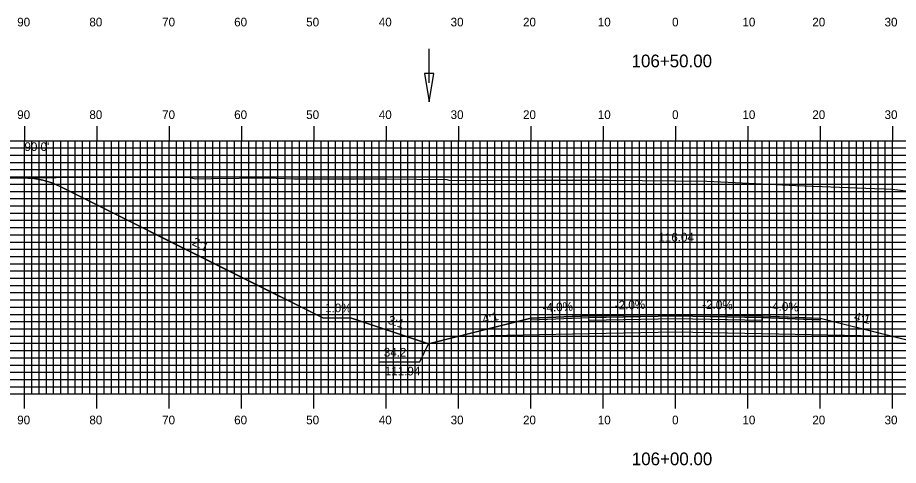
# Model space of a CAD drawing. Extents: x 1768087 to 1768430, y 442591 to 442811.
# Drawn here: x 1768162 to 1768283.8, y 442653.8 to 442715.7 of the extents above; entities that cross this region are included whole.
import ezdxf

# ---------------------------------------------------------------- set-up
doc = ezdxf.new("R2010")
doc.units = 0
for name, color, linetype in [('ANNOTATION', 7, 'Continuous'), ('D_Drainage_Ditch_Line', 7, 'Continuous'), ('D_Roadway_Centerline', 7, 'Continuous'), ('D_Roadway_Centerline_Text', 7, 'Continuous'), ('D_Roadway_Edge_Shoulder', 7, 'Continuous'), ('D_Roadway_Edge_TW', 7, 'Continuous'), ('D_Roadway_Pavement', 7, 'Continuous'), ('D_Roadway_SlopeLines', 7, 'Continuous'), ('D_Roadway_SubGrade', 7, 'Continuous'), ('D_Text_Standard', 7, 'Continuous'), ('H_V ANNOTATION', 7, 'Continuous'), ('MAJOR', 7, 'Continuous'), ('MINOR', 7, 'Continuous'), ('S_Roadway_Centerline', 7, 'Continuous')]:
    doc.layers.add(name, color=color, linetype=linetype)

msp = doc.modelspace()

# ---------------------------------------------------------------- linework, layer by layer
at = {"layer": 'ANNOTATION'}
msp.add_lwpolyline([(1768211.89, 442668.1), (1768217.58, 442668.1), (1768218.79, 442670.6)], dxfattribs=at)
at = {"layer": 'D_Drainage_Ditch_Line'}
msp.add_line((1768218.9, 442706.66), (1768218.9, 442711.36), dxfattribs=at)
msp.add_lwpolyline([(1768219.56, 442707.97), (1768218.24, 442707.97), (1768218.9, 442704.03)], close=True, dxfattribs=at)
at = {"layer": 'D_Roadway_Centerline'}
msp.add_lwpolyline([(1768162.96, 442693.52), (1768163.41, 442693.5), (1768164.21, 442693.46), (1768164.78, 442693.35), (1768165.46, 442693.23), (1768166.44, 442692.93), (1768166.71, 442692.85), (1768167.25, 442692.61), (1768167.96, 442692.3), (1768192.44, 442680.06), (1768204.19, 442674.19), (1768208.16, 442674.15), (1768213.42, 442672.39), (1768218.79, 442670.6), (1768222.79, 442671.6), (1768222.79, 442671.6), (1768230.68, 442673.58), (1768232.96, 442674.15), (1768232.96, 442674.15), (1768232.96, 442674.15), (1768240.96, 442674.47), (1768240.97, 442674.47), (1768250.05, 442674.65), (1768252.96, 442674.71), (1768264.96, 442674.47), (1768270.99, 442674.23), (1768272.96, 442674.15), (1768277.03, 442673.13), (1768283.14, 442671.6), (1768283.14, 442671.6), (1768287.14, 442670.6)], dxfattribs=at)
at = {"layer": 'D_Roadway_Edge_Shoulder'}
for points in [[(1768240.96, 442674.47), (1768232.96, 442674.15), (1768232.96, 442673.9), (1768240.96, 442674.22)], [(1768264.96, 442674.47), (1768272.96, 442674.15), (1768272.96, 442673.9), (1768264.96, 442674.22)]]:
    msp.add_lwpolyline(points, close=True, dxfattribs=at)
at = {"layer": 'D_Roadway_Edge_TW'}
msp.add_lwpolyline([(1768240.96, 442674.22), (1768240.96, 442674.47), (1768252.96, 442674.71), (1768264.96, 442674.47), (1768264.96, 442674.22), (1768252.96, 442674.46)], close=True, dxfattribs=at)
at = {"layer": 'D_Roadway_Pavement'}
msp.add_lwpolyline([(1768240.96, 442673.8), (1768240.96, 442674.22), (1768252.96, 442674.46), (1768264.96, 442674.22), (1768264.96, 442673.8), (1768252.96, 442674.04)], close=True, dxfattribs=at)
at = {"layer": 'D_Roadway_SlopeLines'}
for points in [[(1768208.16, 442674.15), (1768204.19, 442674.19), (1768167.96, 442692.3), (1768166.71, 442692.85), (1768165.46, 442693.23), (1768164.21, 442693.46), (1768162.96, 442693.52)], [(1768218.79, 442670.6), (1768208.16, 442674.15)], [(1768232.96, 442674.15), (1768218.79, 442670.6)], [(1768272.96, 442674.15), (1768287.14, 442670.6)]]:
    msp.add_lwpolyline(points, dxfattribs=at)
at = {"layer": 'D_Roadway_SubGrade'}
msp.add_lwpolyline([(1768240.96, 442671.97), (1768222.79, 442671.6), (1768232.96, 442674.15), (1768232.96, 442673.9), (1768240.96, 442674.22), (1768252.96, 442674.46), (1768264.96, 442674.22), (1768272.96, 442673.9), (1768272.96, 442674.15), (1768283.14, 442671.6), (1768264.96, 442671.97), (1768252.96, 442672.21)], close=True, dxfattribs=at)
at = {"layer": 'MAJOR'}
for p, q in [((1768162.96, 442700.67), (1768162.96, 442698.67)), ((1768172.96, 442700.67), (1768172.96, 442698.67)), ((1768182.96, 442700.67), (1768182.96, 442698.67)), ((1768192.96, 442700.67), (1768192.96, 442698.67)), ((1768202.96, 442700.67), (1768202.96, 442698.67)), ((1768212.96, 442700.67), (1768212.96, 442698.67)), ((1768222.96, 442700.67), (1768222.96, 442698.67)), ((1768232.96, 442700.67), (1768232.96, 442698.67)), ((1768242.96, 442700.67), (1768242.96, 442698.67)), ((1768252.96, 442700.67), (1768252.96, 442698.67)), ((1768262.96, 442700.67), (1768262.96, 442698.67)), ((1768272.96, 442700.67), (1768272.96, 442698.67)), ((1768282.96, 442700.67), (1768282.96, 442698.67)), ((1768112.96, 442698.67), (1768392.96, 442698.67)), ((1768112.96, 442698.67), (1768392.96, 442698.67)), ((1768162.96, 442663.67), (1768162.96, 442698.67)), ((1768172.96, 442663.67), (1768172.96, 442698.67)), ((1768182.96, 442663.67), (1768182.96, 442698.67)), ((1768192.96, 442663.67), (1768192.96, 442698.67)), ((1768202.96, 442663.67), (1768202.96, 442698.67)), ((1768212.96, 442663.67), (1768212.96, 442698.67)), ((1768222.96, 442663.67), (1768222.96, 442698.67)), ((1768232.96, 442663.67), (1768232.96, 442698.67)), ((1768242.96, 442663.67), (1768242.96, 442698.67)), ((1768252.96, 442663.67), (1768252.96, 442698.67)), ((1768262.96, 442663.67), (1768262.96, 442698.67)), ((1768272.96, 442663.67), (1768272.96, 442698.67)), ((1768282.96, 442663.67), (1768282.96, 442698.67)), ((1768112.96, 442693.67), (1768392.96, 442693.67)), ((1768112.96, 442688.67), (1768392.96, 442688.67)), ((1768112.96, 442683.67), (1768392.96, 442683.67)), ((1768112.96, 442678.67), (1768392.96, 442678.67)), ((1768112.96, 442673.67), (1768392.96, 442673.67)), ((1768112.96, 442668.67), (1768392.96, 442668.67)), ((1768112.96, 442663.67), (1768392.96, 442663.67)), ((1768112.96, 442663.67), (1768392.96, 442663.67)), ((1768162.96, 442661.66), (1768162.96, 442663.67)), ((1768172.96, 442661.66), (1768172.96, 442663.67)), ((1768182.96, 442661.66), (1768182.96, 442663.67)), ((1768192.96, 442661.66), (1768192.96, 442663.67)), ((1768202.96, 442661.66), (1768202.96, 442663.67)), ((1768212.96, 442661.66), (1768212.96, 442663.67)), ((1768222.96, 442661.66), (1768222.96, 442663.67)), ((1768232.96, 442661.66), (1768232.96, 442663.67)), ((1768242.96, 442661.66), (1768242.96, 442663.67)), ((1768252.96, 442661.66), (1768252.96, 442663.67)), ((1768262.96, 442661.66), (1768262.96, 442663.67)), ((1768272.96, 442661.66), (1768272.96, 442663.67)), ((1768282.96, 442661.66), (1768282.96, 442663.67))]:
    msp.add_line(p, q, dxfattribs=at)
at = {"layer": 'MINOR'}
for p, q in [((1768163.96, 442663.67), (1768163.96, 442698.67)), ((1768164.96, 442663.67), (1768164.96, 442698.67)), ((1768165.96, 442663.67), (1768165.96, 442698.67)), ((1768166.96, 442663.67), (1768166.96, 442698.67)), ((1768167.96, 442663.67), (1768167.96, 442698.67)), ((1768168.96, 442663.67), (1768168.96, 442698.67)), ((1768169.96, 442663.67), (1768169.96, 442698.67)), ((1768170.96, 442663.67), (1768170.96, 442698.67)), ((1768171.96, 442663.67), (1768171.96, 442698.67)), ((1768173.96, 442663.67), (1768173.96, 442698.67)), ((1768174.96, 442663.67), (1768174.96, 442698.67)), ((1768175.96, 442663.67), (1768175.96, 442698.67)), ((1768176.96, 442663.67), (1768176.96, 442698.67)), ((1768177.96, 442663.67), (1768177.96, 442698.67)), ((1768178.96, 442663.67), (1768178.96, 442698.67)), ((1768179.96, 442663.67), (1768179.96, 442698.67)), ((1768180.96, 442663.67), (1768180.96, 442698.67)), ((1768181.96, 442663.67), (1768181.96, 442698.67)), ((1768183.96, 442663.67), (1768183.96, 442698.67)), ((1768184.96, 442663.67), (1768184.96, 442698.67)), ((1768185.96, 442663.67), (1768185.96, 442698.67)), ((1768186.96, 442663.67), (1768186.96, 442698.67)), ((1768187.96, 442663.67), (1768187.96, 442698.67)), ((1768188.96, 442663.67), (1768188.96, 442698.67)), ((1768189.96, 442663.67), (1768189.96, 442698.67)), ((1768190.96, 442663.67), (1768190.96, 442698.67)), ((1768191.96, 442663.67), (1768191.96, 442698.67)), ((1768193.96, 442663.67), (1768193.96, 442698.67)), ((1768194.96, 442663.67), (1768194.96, 442698.67)), ((1768195.96, 442663.67), (1768195.96, 442698.67)), ((1768196.96, 442663.67), (1768196.96, 442698.67)), ((1768197.96, 442663.67), (1768197.96, 442698.67)), ((1768198.96, 442663.67), (1768198.96, 442698.67)), ((1768199.96, 442663.67), (1768199.96, 442698.67)), ((1768200.96, 442663.67), (1768200.96, 442698.67)), ((1768201.96, 442663.67), (1768201.96, 442698.67)), ((1768203.96, 442663.67), (1768203.96, 442698.67)), ((1768204.96, 442663.67), (1768204.96, 442698.67)), ((1768205.96, 442663.67), (1768205.96, 442698.67)), ((1768206.96, 442663.67), (1768206.96, 442698.67)), ((1768207.96, 442663.67), (1768207.96, 442698.67)), ((1768208.96, 442663.67), (1768208.96, 442698.67)), ((1768209.96, 442663.67), (1768209.96, 442698.67)), ((1768210.96, 442663.67), (1768210.96, 442698.67)), ((1768211.96, 442663.67), (1768211.96, 442698.67)), ((1768213.96, 442663.67), (1768213.96, 442698.67)), ((1768214.96, 442663.67), (1768214.96, 442698.67)), ((1768215.96, 442663.67), (1768215.96, 442698.67)), ((1768216.96, 442663.67), (1768216.96, 442698.67)), ((1768217.96, 442663.67), (1768217.96, 442698.67)), ((1768218.96, 442663.67), (1768218.96, 442698.67)), ((1768219.96, 442663.67), (1768219.96, 442698.67)), ((1768220.96, 442663.67), (1768220.96, 442698.67)), ((1768221.96, 442663.67), (1768221.96, 442698.67)), ((1768223.96, 442663.67), (1768223.96, 442698.67)), ((1768224.96, 442663.67), (1768224.96, 442698.67)), ((1768225.96, 442663.67), (1768225.96, 442698.67)), ((1768226.96, 442663.67), (1768226.96, 442698.67)), ((1768227.96, 442663.67), (1768227.96, 442698.67)), ((1768228.96, 442663.67), (1768228.96, 442698.67)), ((1768229.96, 442663.67), (1768229.96, 442698.67)), ((1768230.96, 442663.67), (1768230.96, 442698.67)), ((1768231.96, 442663.67), (1768231.96, 442698.67)), ((1768233.96, 442663.67), (1768233.96, 442698.67)), ((1768234.96, 442663.67), (1768234.96, 442698.67)), ((1768235.96, 442663.67), (1768235.96, 442698.67)), ((1768236.96, 442663.67), (1768236.96, 442698.67)), ((1768237.96, 442663.67), (1768237.96, 442698.67)), ((1768238.96, 442663.67), (1768238.96, 442698.67)), ((1768239.96, 442663.67), (1768239.96, 442698.67)), ((1768240.96, 442663.67), (1768240.96, 442698.67)), ((1768241.96, 442663.67), (1768241.96, 442698.67)), ((1768243.96, 442663.67), (1768243.96, 442698.67)), ((1768244.96, 442663.67), (1768244.96, 442698.67)), ((1768245.96, 442663.67), (1768245.96, 442698.67)), ((1768246.96, 442663.67), (1768246.96, 442698.67)), ((1768247.96, 442663.67), (1768247.96, 442698.67)), ((1768248.96, 442663.67), (1768248.96, 442698.67)), ((1768249.96, 442663.67), (1768249.96, 442698.67)), ((1768250.96, 442663.67), (1768250.96, 442698.67)), ((1768251.96, 442663.67), (1768251.96, 442698.67)), ((1768253.96, 442663.67), (1768253.96, 442698.67)), ((1768254.96, 442663.67), (1768254.96, 442698.67)), ((1768255.96, 442663.67), (1768255.96, 442698.67)), ((1768256.96, 442663.67), (1768256.96, 442698.67)), ((1768257.96, 442663.67), (1768257.96, 442698.67)), ((1768258.96, 442663.67), (1768258.96, 442698.67)), ((1768259.96, 442663.67), (1768259.96, 442698.67)), ((1768260.96, 442663.67), (1768260.96, 442698.67)), ((1768261.96, 442663.67), (1768261.96, 442698.67)), ((1768263.96, 442663.67), (1768263.96, 442698.67)), ((1768264.96, 442663.67), (1768264.96, 442698.67)), ((1768265.96, 442663.67), (1768265.96, 442698.67)), ((1768266.96, 442663.67), (1768266.96, 442698.67)), ((1768267.96, 442663.67), (1768267.96, 442698.67)), ((1768268.96, 442663.67), (1768268.96, 442698.67)), ((1768269.96, 442663.67), (1768269.96, 442698.67)), ((1768270.96, 442663.67), (1768270.96, 442698.67)), ((1768271.96, 442663.67), (1768271.96, 442698.67)), ((1768273.96, 442663.67), (1768273.96, 442698.67)), ((1768274.96, 442663.67), (1768274.96, 442698.67)), ((1768275.96, 442663.67), (1768275.96, 442698.67)), ((1768276.96, 442663.67), (1768276.96, 442698.67)), ((1768277.96, 442663.67), (1768277.96, 442698.67)), ((1768278.96, 442663.67), (1768278.96, 442698.67)), ((1768279.96, 442663.67), (1768279.96, 442698.67)), ((1768280.96, 442663.67), (1768280.96, 442698.67)), ((1768281.96, 442663.67), (1768281.96, 442698.67)), ((1768112.96, 442697.67), (1768392.96, 442697.67)), ((1768112.96, 442696.67), (1768392.96, 442696.67)), ((1768112.96, 442695.67), (1768392.96, 442695.67)), ((1768112.96, 442694.67), (1768392.96, 442694.67)), ((1768112.96, 442692.67), (1768392.96, 442692.67)), ((1768112.96, 442691.67), (1768392.96, 442691.67)), ((1768112.96, 442690.67), (1768392.96, 442690.67)), ((1768112.96, 442689.67), (1768392.96, 442689.67)), ((1768112.96, 442687.67), (1768392.96, 442687.67)), ((1768112.96, 442686.67), (1768392.96, 442686.67)), ((1768112.96, 442685.67), (1768392.96, 442685.67)), ((1768112.96, 442684.67), (1768392.96, 442684.67)), ((1768112.96, 442682.67), (1768392.96, 442682.67)), ((1768112.96, 442681.67), (1768392.96, 442681.67)), ((1768112.96, 442680.67), (1768392.96, 442680.67)), ((1768112.96, 442679.67), (1768392.96, 442679.67)), ((1768112.96, 442677.67), (1768392.96, 442677.67)), ((1768112.96, 442676.67), (1768392.96, 442676.67)), ((1768112.96, 442675.67), (1768392.96, 442675.67)), ((1768112.96, 442674.67), (1768392.96, 442674.67)), ((1768112.96, 442672.67), (1768392.96, 442672.67)), ((1768112.96, 442671.67), (1768392.96, 442671.67)), ((1768112.96, 442670.67), (1768392.96, 442670.67)), ((1768112.96, 442669.67), (1768392.96, 442669.67)), ((1768112.96, 442667.67), (1768392.96, 442667.67)), ((1768112.96, 442666.67), (1768392.96, 442666.67)), ((1768112.96, 442665.67), (1768392.96, 442665.67)), ((1768112.96, 442664.67), (1768392.96, 442664.67))]:
    msp.add_line(p, q, dxfattribs=at)
at = {"layer": 'S_Roadway_Centerline'}
msp.add_lwpolyline([(1768153.09, 442693.4), (1768167.33, 442693.57), (1768172.21, 442693.63), (1768184.82, 442693.6), (1768185.59, 442693.61), (1768186.64, 442693.41), (1768188.8, 442693.43), (1768196.51, 442693.55), (1768200.19, 442693.42), (1768212.53, 442693.4), (1768212.78, 442693.42), (1768213.06, 442693.42), (1768221.33, 442693.3), (1768221.59, 442693.24), (1768224.33, 442693.19), (1768233.58, 442693.21), (1768243.7, 442693.22), (1768248.33, 442693.19), (1768257.28, 442693.06), (1768263.15, 442692.79), (1768269.58, 442692.46), (1768280.49, 442692.05), (1768282.01, 442692.02), (1768282.89, 442691.98), (1768286.37, 442691.56)], dxfattribs=at)

# ---------------------------------------------------------------- texts
at = {"layer": 'ANNOTATION'}
for s, rotation, p in [('2:1', 333.4347, (1768186.01, 442684.31)), ('-4.0%', 2.2905, (1768234.6, 442675.01)), ('-2.0%', 1.1458, (1768244.57, 442675.34)), ('-2.0%', 358.8542, (1768256.65, 442675.43)), ('-4.0%', 357.7091, (1768265.77, 442675.24)), ('1.0%', 359.4365, (1768204.5, 442674.98)), ('3:1', 341.563, (1768213.08, 442673.41)), ('4:1', 14.0384, (1768226.41, 442673.37)), ('4:1', 345.9623, (1768277.55, 442673.86))]:
    msp.add_text(s, height=1.2, rotation=rotation, dxfattribs=at).set_placement(p)
for s, p in [("34.2'", (1768212.62, 442668.83)), ('111.94', (1768212.76, 442666.23))]:
    msp.add_text(s, height=1.2, dxfattribs=at).set_placement(p)
at = {"layer": 'D_Roadway_Centerline'}
for s, p in [('C', (1768252.96, 442674.71)), ('L', (1768252.96, 442674.7))]:
    msp.add_text(s, height=0.0146, dxfattribs=at).set_placement(p)
at = {"layer": 'D_Roadway_Centerline_Text'}
msp.add_text('116.04', height=1.2, dxfattribs=at).set_placement((1768250.59, 442684.74))
at = {"layer": 'D_Text_Standard'}
msp.add_text("90.0'", height=1.2, dxfattribs=at).set_placement((1768162.93, 442697.25))
at = {"layer": 'H_V ANNOTATION'}
for s, height, p in [('90', 1.2, (1768161.93, 442714.47)), ('80', 1.2, (1768171.91, 442714.47)), ('70', 1.2, (1768181.97, 442714.47)), ('60', 1.2, (1768191.93, 442714.47)), ('50', 1.2, (1768201.89, 442714.47)), ('40', 1.2, (1768211.93, 442714.47)), ('30', 1.2, (1768221.86, 442714.47)), ('20', 1.2, (1768231.87, 442714.47)), ('10', 1.2, (1768242.21, 442714.47)), ('0', 1.2, (1768252.48, 442714.47)), ('10', 1.2, (1768262.21, 442714.47)), ('20', 1.2, (1768271.87, 442714.47)), ('30', 1.2, (1768281.86, 442714.47)), ('106+50.00', 1.75, (1768246.88, 442708.82)), ('90', 1.2, (1768161.93, 442701.67)), ('80', 1.2, (1768171.91, 442701.67)), ('70', 1.2, (1768181.97, 442701.67)), ('60', 1.2, (1768191.93, 442701.67)), ('50', 1.2, (1768201.89, 442701.67)), ('40', 1.2, (1768211.93, 442701.67)), ('30', 1.2, (1768221.86, 442701.67)), ('20', 1.2, (1768231.87, 442701.67)), ('10', 1.2, (1768242.21, 442701.67)), ('0', 1.2, (1768252.48, 442701.67)), ('10', 1.2, (1768262.21, 442701.67)), ('20', 1.2, (1768271.87, 442701.67)), ('30', 1.2, (1768281.86, 442701.67)), ('90', 1.2, (1768161.93, 442659.47)), ('80', 1.2, (1768171.91, 442659.47)), ('70', 1.2, (1768181.97, 442659.47)), ('60', 1.2, (1768191.93, 442659.47)), ('50', 1.2, (1768201.89, 442659.47)), ('40', 1.2, (1768211.93, 442659.47)), ('30', 1.2, (1768221.86, 442659.47)), ('20', 1.2, (1768231.87, 442659.47)), ('10', 1.2, (1768242.21, 442659.47)), ('0', 1.2, (1768252.48, 442659.47)), ('10', 1.2, (1768262.21, 442659.47)), ('20', 1.2, (1768271.87, 442659.47)), ('30', 1.2, (1768281.86, 442659.47)), ('106+00.00', 1.75, (1768246.91, 442653.82))]:
    msp.add_text(s, height=height, dxfattribs=at).set_placement(p)

doc.saveas('drawing.dxf')
